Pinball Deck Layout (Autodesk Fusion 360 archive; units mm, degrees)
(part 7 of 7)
extrude "Extrude143" cut sketch "Flipper 90" profile of C1 C3 blind -20 from offset -25.3
sweep "Sweep11" sketch "Rubber Band profile" TwistAngle 0 TaperAngle 0
fillet "Fillet16" radius 2
extrude "Extrude144" new body sketch "Flipper 90" along normal blind 25 bodies "Fliper 90 + 4"
extrude "Extrude145" new body sketch "Flipper 90" profile of C1 L1 L2 C2 C3 against normal blind 35.2
combine "Combine3"
extrude "Extrude146" cut sketch "Flipper 90" profile of L1 L2 C2 blind -20 taper 3 from offset -26.3
extrude "Extrude147" cut sketch "Flipper 90" profile of C1 C3 blind -20 from offset -26
sweep "Sweep12" sketch "Rubber Band profile" TwistAngle 0 TaperAngle 0
fillet "Fillet17" radius 2
extrude "Extrude148" new body sketch "Solenoid Coupling" along normal blind 1.5 and against normal blind 1.5 bodies "Solenoid Coupling 37mm"
extrude "Extrude149" cut sketch "Coupling base labelling" blind 0.4 from offset 0.3
extrude "Extrude150" new body sketch "Solenoid Coupling" along normal blind 1.5 and against normal blind 1.5 bodies "Solenoid Coupling 36mm"
extrude "Extrude151" cut sketch "Coupling base labelling" blind 0.4 from offset 0.4
extrude "Extrude152" add sketch "Solenoid Coupling" along normal blind 7.5 and against normal blind 7.5
extrude "Extrude153" add sketch "Solenoid Coupling" along normal blind 7.5 and against normal blind 7.5
extrude "Extrude154" add sketch "Solenoid Coupling" blind 3 from offset 4.5
extrude "Extrude155" add sketch "Solenoid Coupling" blind -3 from offset -4.5
extrude "Extrude156" add sketch "Solenoid Coupling" blind 3 from offset 4.5
extrude "Extrude157" add sketch "Solenoid Coupling" blind -3 from offset -4.5
sketch "Double Drive Flipper Mirrored" plane through (0, 0, -10.2) normal (0, 0, 1) x axis (1, 0, 0)
  line L1 (-80, -27) -> (80, -27)
  line L2 (80, 27) -> (-80, 27)
  line L3 (-80, 27) -> (-80, -27)
  line L4 (80, -27) -> (80, 27)
  line L5 (-80, 27) -> (80, 27)
  line L6 (-80, -27) -> (-80, 27)
  line L7 (80, -27) -> (-80, -27)
  line L8 (80, 27) -> (80, -27)
  circle C1 centre (-56.5, -14.5) radius 1.8
  circle C2 centre (-71.5, -2.5) radius 1.8
  circle C3 centre (0, 0) radius 7.3
  circle C4 centre (74, -21) radius 2.25
  circle C5 centre (71.5, 2.5) radius 4
  circle C6 centre (71.5, 2.5) radius 1.8
  circle C7 centre (-74, 21) radius 2.25
  circle C8 centre (-44, -21) radius 4
  circle C9 centre (44, 21) radius 2.25
  circle C10 centre (-44, -21) radius 2.25
  circle C11 centre (44, 21) radius 4
  circle C12 centre (-71.5, -2.5) radius 4
  circle C13 centre (-56.5, -14.5) radius 4
  circle C14 centre (56.5, 14.5) radius 1.8
  circle C15 centre (74, -21) radius 4
  circle C16 centre (56.5, 14.5) radius 4
  circle C17 centre (-74, 21) radius 4
  circle C18 centre (-74, -21) radius 2.25
  circle C19 centre (0, 0) radius 11
  circle C20 centre (-11.3357, -19.6167) radius 1.75
  circle C21 centre (-11.3357, -19.6167) radius 4
  circle C22 centre (22.1977, -3.9798) radius 1.75
  circle C23 centre (22.1977, -3.9798) radius 4
  circle C24 centre (-22.3238, 3.9473) radius 1.75
  circle C25 centre (-22.3238, 3.9473) radius 4
  circle C26 centre (11.2096, 19.5842) radius 1.75
  circle C27 centre (11.2096, 19.5842) radius 4
  point P5 (0, 0)
  point P7 (0, 0)
  horizontal L2
  perpendicular L2 L4
  perpendicular L1 L4
  perpendicular L2 L3
  coincident P5 P7
  concentric C7 C17
  concentric C8 C10
  concentric C9 C11
  concentric C4 C15
  concentric C2 C12
  concentric C1 C13
  concentric C14 C16
  concentric C5 C6
  concentric C20 C21
  concentric C24 C25
  concentric C22 C23
  concentric C26 C27
  dimension "d911" diameter C7 = 4.5
  dimension "d912" diameter C17 = 8
  dimension "d913" diameter C10 = 4.5
  dimension "d914" diameter C8 = 8
  dimension "d915" diameter C9 = 4.5
  dimension "d916" diameter C11 = 8
  dimension "d917" diameter C4 = 4.5
  dimension "d918" diameter C15 = 8
  dimension "d919" diameter C12 = 8
  dimension "d920" diameter C13 = 8
  dimension "d921" diameter C16 = 8
  dimension "d922" diameter C5 = 8
  dimension "d923" diameter C20 = 3.5
  dimension "d924" diameter C21 = 8
  dimension "d925" diameter C24 = 3.5
  dimension "d926" diameter C25 = 8
  dimension "d927" diameter C22 = 3.5
  dimension "d928" diameter C23 = 8
  dimension "d929" diameter C26 = 3.5
  dimension "d930" diameter C27 = 8
extrude "Extrude159" new body sketch "Double Drive Flipper Mirrored" against normal blind 10 bodies "Double Drive 9mm Deck Mirrored"
extrude "Extrude160" cut sketch "Double Drive Flipper Mirrored" profile of C1 C2 C5 C6 C12 C13 C14 C16 against normal blind 6
extrude "Extrude161" cut sketch "Double Drive Flipper Mirrored" profile of C20 C21 C22 C23 C24 C25 C26 C27 against normal blind 6
extrude "Extrude162" add sketch "Double Drive Flipper Mirrored" profile of C3 C19 along normal blind 12.6
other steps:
base_feature "Base Feature" bodies "Base and Bushing", "Base and Bushing 12mm deck"
named bodies: "DO NOT USE FLIPPER PROTO", "Washer Upper", "Base and Bushing 9mm deck", "Base Section", "Solenoid 22mm", "Solenoid 37mm", "Flipper Drive", "Washer Lower", "Drive Arm Washer", "Solenoid Coupling 38mm", "Solenoid Coupling 41mm", "Solenoid Coupling 42mm", "Solenoid Coupling 40mm", "Solenoid Coupling 43mm", "Solenoid Coupling 39mm", "Bushing + 1", "Washer 0.6", "Solenoid Coupling 47mm", "Solenoid Coupling 45mm", "Flipper_Straight", "Flipper Straight + 1", "Drive Limiter", "Drive Limiter Mirrored", "Base and Bushing 9mm deck Mirrored", "Flipper Drive Mirrored", "Base and Bushing", "Base and Bushing 12mm deck", "Base and Bushing 12mm deck Mirrored", "Flipper + 2", "Flipper + 3", "Flipper + 4", "Double Drive 9mm deck", "Flipper Drive Double", "Solenoid Coupling Double 41mm", "Solenoid 22mm Double", "Solenoid 22mm Double 2", "Drive Limiter Double", "Flipper Drive Double Mirrored", "Flipper 90", "Flipper 90 + 1", "Flipper 90 + 2", "Flipper 90 + 3", "Fliper 90 + 4", "Solenoid Coupling 37mm", "Solenoid Coupling 36mm", "Double Drive 9mm Deck Mirrored"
